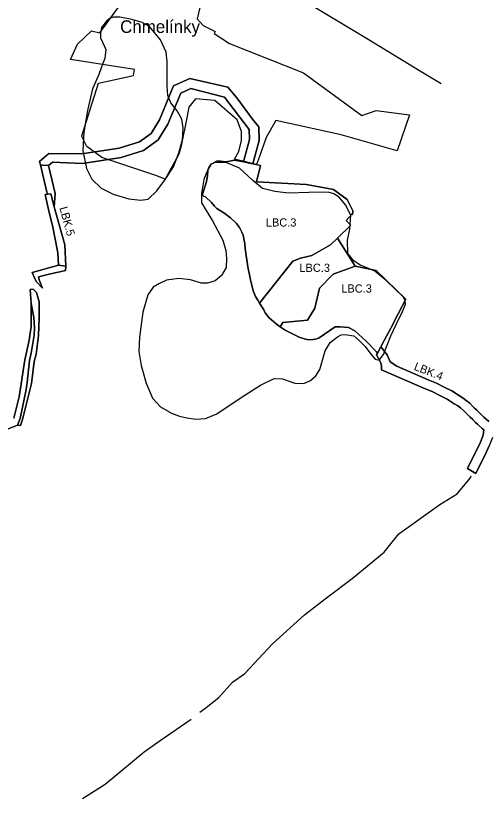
# Model space of a CAD drawing. Extents: x -555426 to -553015, y -1186745 to -1182595.
# Drawn here: x -554287 to -553542, y -1186745 to -1185506 of the extents above; entities that cross this region are included whole.
import ezdxf

# ---------------------------------------------------------------- set-up
doc = ezdxf.new("R2010")
doc.units = 0
for name, color, linetype in [('Level 10', 7, 'Continuous'), ('Level 12', 7, 'Continuous'), ('Level 14', 7, 'Continuous'), ('Level 51', 7, 'Continuous'), ('svahove_deformace', 7, 'Continuous'), ('USES_ID', 7, 'Continuous'), ('USES_LBC_navrh', 7, 'Continuous'), ('USES_LBC_stav', 7, 'Continuous'), ('USES_LBK_navrh', 7, 'Continuous'), ('USES_LBK_stav', 7, 'Continuous')]:
    doc.layers.add(name, color=color, linetype=linetype)

msp = doc.modelspace()

# ---------------------------------------------------------------- linework, layer by layer
at = {"layer": 'Level 10'}
msp.add_lwpolyline([(-553975.4, -1185407.1), (-553999.7, -1185510.6), (-553990.3, -1185521.1), (-553971.3, -1185530.6), (-553972.7, -1185533.8), (-553948.4, -1185549.8), (-553831.6, -1185596.5), (-553739, -1185663.9), (-553716.5, -1185656), (-553663.6, -1185662.6), (-553683.4, -1185719.5), (-553771.6, -1185694.6), (-553875.2, -1185671.9), (-553890.2, -1185698.9), (-553900.8, -1185728.5), (-553905.9, -1185741.4), (-553940.6, -1185733.1), (-553933.4, -1185720.8), (-553929.5, -1185703.6), (-553929.5, -1185689.1), (-553936.1, -1185670.6), (-553971.8, -1185640.1), (-554002.2, -1185637.5), (-554012.8, -1185650.7), (-554016.1, -1185667.5), (-554024.7, -1185711.6), (-554028.7, -1185724.8), (-554049.9, -1185764.5), (-554065, -1185758.6), (-554150.4, -1185730.1), (-554174.2, -1185712.9), (-554181.7, -1185697.3), (-554181.9, -1185696), (-554155.7, -1185612.4), (-554100.1, -1185600.4), (-554098.8, -1185591.2), (-554200.1, -1185574.9), (-554188.6, -1185550.7), (-554166.6, -1185529.6), (-554153.6, -1185532.9), (-554122.2, -1185490.3)], dxfattribs=at)
at = {"layer": 'Level 12'}
for points in [[(-553911.7, -1185740.4), (-553901.7, -1185703.4), (-553902.2, -1185681.8), (-553910.4, -1185671.8), (-553936.7, -1185635.6), (-553950.9, -1185618.8), (-554011.3, -1185605.1), (-554036.9, -1185617.1), (-554059.2, -1185670.5), (-554072.4, -1185692.2), (-554091, -1185705.4), (-554123, -1185715.5), (-554181.9, -1185724.6), (-554234, -1185724.1), (-554248.9, -1185736.6), (-554247.6, -1185742.1), (-554237.4, -1185785.1), (-554235.8, -1185788.4), (-554240, -1185789.1), (-554233.4, -1185817.2), (-554228.1, -1185837.8), (-554220, -1185881.2), (-554219, -1185900.7)], [(-554219, -1185900.7), (-554260.6, -1185912.2), (-554256.7, -1185920.6), (-554254.1, -1185926.6), (-554244.3, -1185937.4), (-554249.6, -1185923.8), (-554250.3, -1185919.1), (-554231.4, -1185914.6), (-554219.4, -1185911.8), (-554216.8, -1185911.1), (-554208, -1185909), (-554207.5, -1185902.6), (-554208.9, -1185868.4), (-554225.5, -1185808.2), (-554224.1, -1185787.4), (-554234.7, -1185743.1), (-554228.1, -1185737.6), (-554180.8, -1185739.6), (-554119.6, -1185730.2), (-554084.2, -1185719), (-554061.2, -1185702.6), (-554045.8, -1185677.3), (-554025.3, -1185628.3), (-554009.8, -1185620.9), (-553956.2, -1185634.8), (-553917.3, -1185685.8), (-553916.8, -1185701.6), (-553926.4, -1185737.4)], [(-554249.4, -1185959), (-554253.8, -1185944), (-554258.9, -1185938.8), (-554263.5, -1185939.1), (-554261.9, -1185961.7), (-554261.9, -1185997.8), (-554265.3, -1186019.4), (-554272.3, -1186050.7), (-554281.2, -1186109.2), (-554289.5, -1186143)], [(-554377.3, -1186191), (-554283.7, -1186154), (-554278.9, -1186154.8), (-554275.9, -1186144.9), (-554261.8, -1186087.9), (-554257.2, -1186053.5), (-554254.2, -1186041.6), (-554250.5, -1186012.3), (-554249.2, -1185984.3), (-554249.4, -1185959)], [(-553538.1, -1186148.4), (-553546, -1186141.3), (-553548.7, -1186138.9), (-553553, -1186134.5), (-553557.1, -1186130.6), (-553560.6, -1186127.2), (-553563.8, -1186123.8), (-553568.3, -1186119.3), (-553574.1, -1186115), (-553578.7, -1186111.4), (-553584.6, -1186107.6), (-553596.5, -1186099.9), (-553608.8, -1186093.7), (-553621.2, -1186087.4), (-553633.9, -1186082.1), (-553683.5, -1186060.8), (-553694.2, -1186053.6), (-553699.1, -1186042.7), (-553709.2, -1186029.9)], [(-553714.5, -1186040.1), (-553716, -1186043), (-553709.2, -1186055.2), (-553707.9, -1186060.7), (-553707.8, -1186066.7), (-553639.7, -1186095.9), (-553627.6, -1186101), (-553615.6, -1186107), (-553604, -1186112.9), (-553592.8, -1186120.2), (-553587.3, -1186123.7), (-553583.1, -1186126.9), (-553578.2, -1186130.7), (-553574.5, -1186134.4), (-553571.2, -1186137.7), (-553567.7, -1186141.3), (-553563.5, -1186145.2), (-553559.1, -1186149.7), (-553556.1, -1186152.4), (-553548, -1186159.7), (-553546.2, -1186161.3), (-553547, -1186170), (-553551.5, -1186181.2), (-553571.7, -1186222.8), (-553558.8, -1186230.6), (-553551.7, -1186216.3), (-553544.7, -1186202.1), (-553537.6, -1186186.9)]]:
    msp.add_lwpolyline(points, dxfattribs=at)
at = {"layer": 'Level 14'}
msp.add_lwpolyline([(-553940.3, -1185734.7), (-553953.7, -1185737.4), (-553967.2, -1185735.6), (-553977.6, -1185741.1), (-553982.8, -1185750.6), (-553983.4, -1185759.1), (-553984.9, -1185768.3), (-553991.5, -1185790.7), (-553986.1, -1185792.8), (-553977.1, -1185801.5), (-553972.2, -1185807.6), (-553968.2, -1185811), (-553955.7, -1185819.2), (-553950.7, -1185823), (-553946.8, -1185825.9), (-553937.5, -1185834.6), (-553932.6, -1185841.2), (-553928.7, -1185848.7), (-553926.8, -1185853.5), (-553925, -1185861.8), (-553924.3, -1185866.6), (-553923.7, -1185874.2), (-553919.6, -1185903.6), (-553916.2, -1185918.5), (-553914.7, -1185926.6), (-553912.2, -1185936.6), (-553911.1, -1185941.6), (-553907.2, -1185950.3), (-553903.5, -1185956.3), (-553900.7, -1185960.7), (-553893.9, -1185971.6), (-553892.2, -1185976.1), (-553885.6, -1185984.2), (-553874.4, -1185993.9), (-553868.1, -1185998.6), (-553860.1, -1186003.8), (-553838.1, -1186014.6), (-553828.2, -1186017.9), (-553822.7, -1186018.8), (-553816.2, -1186018.6), (-553810.1, -1186017.5), (-553806.4, -1186016.1), (-553781.2, -1185998.5), (-553773.2, -1185998.5), (-553759.9, -1185999.4), (-553750.1, -1186005), (-553733, -1186020.5), (-553715.8, -1186038), (-553714.5, -1186040.1), (-553709.2, -1186029.9), (-553704, -1186019.9), (-553693.4, -1186000.3), (-553681.6, -1185977.6), (-553669.6, -1185954.8), (-553716.6, -1185909.4), (-553749.5, -1185902.4), (-553777.3, -1185857.8), (-553756.3, -1185837.6), (-553763.7, -1185830.1), (-553754.7, -1185819.8), (-553753.8, -1185820.7), (-553753.1, -1185814.5), (-553762.3, -1185797), (-553784, -1185781.1), (-553826.5, -1185773.2), (-553905.7, -1185768.8), (-553899.3, -1185742.9), (-553940.3, -1185734.7)], dxfattribs=at)
at = {"layer": 'Level 51'}
for points in [[(-554064, -1185305.3), (-554054.3, -1185313), (-554015.3, -1185345.9), (-553963.7, -1185392), (-553941.6, -1185410.7), (-553882.9, -1185450.1), (-553831.9, -1185481.1), (-553729.3, -1185543.1), (-553648, -1185592.3), (-553613.8, -1185613.3)], [(-553995.2, -1186608.6), (-553985.5, -1186601.4), (-553965.2, -1186585.4), (-553943.8, -1186560.8), (-553924.1, -1186547.3), (-553881.1, -1186500.9), (-553829.5, -1186454.6), (-553797.2, -1186429.2), (-553754.2, -1186397.1), (-553703.6, -1186355.1), (-553680.7, -1186326.3), (-553615.9, -1186279.5), (-553588.3, -1186262.7), (-553567.9, -1186238.2), (-553566, -1186234.2)], [(-554180.7, -1186745), (-554145.3, -1186722.8), (-554083.6, -1186671.3), (-554057.8, -1186653.2), (-554009.1, -1186619.5)]]:
    msp.add_lwpolyline(points, dxfattribs=at)
at = {"layer": 'svahove_deformace'}
for points in [[(-554063.2, -1185783.2), (-554051.2, -1185766.8), (-554036.9, -1185745.3), (-554028.3, -1185722.7), (-554022.9, -1185702.3), (-554021.9, -1185683.5), (-554023.6, -1185669.8), (-554031.4, -1185656.5), (-554041.3, -1185643.9), (-554045.7, -1185631.9), (-554046.8, -1185617.2), (-554047.1, -1185578.3), (-554048.5, -1185563.3), (-554057.7, -1185544.2), (-554074.8, -1185523), (-554086.4, -1185516.5), (-554102.8, -1185511.7), (-554121.9, -1185508.3), (-554132.1, -1185508.3), (-554137.3, -1185509.7), (-554143.1, -1185514.5), (-554150.6, -1185524.7), (-554152.6, -1185533.6), (-554152.6, -1185541.1), (-554146.1, -1185554.8), (-554144.1, -1185559.5), (-554144.8, -1185568.4), (-554145.4, -1185573.5), (-554149.2, -1185582.4), (-554155, -1185598.8), (-554165.2, -1185621.7), (-554173.1, -1185655.8), (-554178.9, -1185690), (-554180.6, -1185719), (-554174.8, -1185747.7), (-554166.3, -1185764.4), (-554151.2, -1185778.7), (-554132.5, -1185788.6), (-554107.5, -1185795.5), (-554088.4, -1185797.8), (-554076.8, -1185796.1), (-554063.2, -1185783.2)], [(-553896.2, -1185779.4), (-553911.6, -1185766.8), (-553932.4, -1185747), (-553946.4, -1185741.2), (-553953.9, -1185738.4), (-553966.9, -1185738.1), (-553972.7, -1185738.8), (-553978.1, -1185740.8), (-553980.9, -1185745.6), (-553989.1, -1185765.1), (-553992.8, -1185787.3), (-553992.5, -1185801.9), (-553975.1, -1185830.6), (-553958.7, -1185861), (-553954.2, -1185877.4), (-553952.9, -1185890), (-553953.9, -1185904.7), (-553961.1, -1185917), (-553971.3, -1185925.5), (-553983.3, -1185929.3), (-553992.8, -1185929.3), (-554009.9, -1185924.2), (-554028.7, -1185921.8), (-554047.8, -1185924.5), (-554060.4, -1185930.3), (-554069.3, -1185935.4), (-554077.5, -1185947.7), (-554085.4, -1185975.4), (-554090.8, -1186014.7), (-554091.8, -1186037.5), (-554088.1, -1186059.4), (-554080.2, -1186087.4), (-554070, -1186111.6), (-554057.7, -1186125.3), (-554039.9, -1186135.2), (-554027.3, -1186140), (-554016, -1186142.7), (-554001.7, -1186144.7), (-553986.3, -1186143.7), (-553968.2, -1186136.2), (-553929.7, -1186110.3), (-553899.6, -1186090.8), (-553877.8, -1186080.5), (-553864.5, -1186080.9), (-553845, -1186087.7), (-553831, -1186088.1), (-553820.1, -1186083.6), (-553811.9, -1186075.8), (-553805.4, -1186066.2), (-553797.2, -1186036.2), (-553789.3, -1186023.2), (-553777.7, -1186014.3), (-553771.9, -1186010.9), (-553765.8, -1186010.6), (-553751.8, -1186012.9), (-553742.9, -1186020.5), (-553733.7, -1186029.7), (-553724.8, -1186041.6), (-553718, -1186049.5), (-553711.8, -1186051.2), (-553705, -1186042.3), (-553693.1, -1186012.9), (-553680.1, -1185984.6), (-553675.6, -1185976.8), (-553669.8, -1185962.4), (-553670.5, -1185957.3), (-553673.9, -1185950.8), (-553700.9, -1185924.5), (-553718.7, -1185910.5), (-553732.3, -1185904.4), (-553741.9, -1185901), (-553751.8, -1185894.1), (-553761.3, -1185882.5), (-553762, -1185861), (-553757.9, -1185843.6), (-553756.6, -1185821.4), (-553764.8, -1185805.4), (-553774.7, -1185793.1), (-553783.5, -1185787.6), (-553792.1, -1185785.2), (-553822.8, -1185785.6), (-553854.9, -1185786.9), (-553876.7, -1185783.9), (-553896.2, -1185779.4)]]:
    msp.add_lwpolyline(points, dxfattribs=at)
at = {"layer": 'USES_LBC_navrh'}
for p, q in [((-553788.7, -1185868.8), (-553777.3, -1185857.8)), ((-553777.3, -1185857.8), (-553749.5, -1185902.4)), ((-553818.4, -1185885.3), (-553788.7, -1185868.8)), ((-553900.7, -1185960.7), (-553848.1, -1185894.5)), ((-553749.5, -1185902.4), (-553784.2, -1185915)), ((-553784.2, -1185915), (-553806.1, -1185937)), ((-553893.9, -1185971.6), (-553900.7, -1185960.7)), ((-553892.2, -1185976.1), (-553893.9, -1185971.6)), ((-553885.6, -1185984.2), (-553892.2, -1185976.1)), ((-553874.4, -1185993.9), (-553885.6, -1185984.2)), ((-553868.1, -1185998.6), (-553874.4, -1185993.9)), ((-553864, -1185991.5), (-553868.1, -1185998.6)), ((-553825.1, -1185988.1), (-553864, -1185991.5))]:
    msp.add_line(p, q, dxfattribs=at)
for points in [[(-553848.1, -1185894.5), (-553836.1, -1185889.5), (-553818.4, -1185885.3)], [(-553806.1, -1185937), (-553813.2, -1185969.1), (-553825.1, -1185988.1)]]:
    msp.add_lwpolyline(points, dxfattribs=at)
at = {"layer": 'USES_LBC_stav'}
for p, q in [((-553868.1, -1185998.6), (-553864, -1185991.5)), ((-553864, -1185991.5), (-553825.1, -1185988.1))]:
    msp.add_line(p, q, dxfattribs=at)
for points in [[(-553900.7, -1185960.7), (-553903.5, -1185956.3), (-553907.2, -1185950.3), (-553911.1, -1185941.6), (-553912.2, -1185936.6), (-553914.7, -1185926.6), (-553916.2, -1185918.5), (-553919.6, -1185903.6), (-553923.7, -1185874.2), (-553924.3, -1185866.6), (-553925, -1185861.8), (-553926.8, -1185853.5), (-553928.7, -1185848.7), (-553932.6, -1185841.2), (-553937.5, -1185834.6), (-553946.8, -1185825.9), (-553950.7, -1185823), (-553955.7, -1185819.2), (-553968.2, -1185811), (-553972.2, -1185807.6), (-553977.1, -1185801.5), (-553986.1, -1185792.8), (-553991.5, -1185790.7), (-553984.9, -1185768.3), (-553983.4, -1185759.1), (-553982.8, -1185750.6), (-553977.6, -1185741.1), (-553967.2, -1185735.6), (-553953.7, -1185737.4), (-553940.3, -1185734.7)], [(-553940.3, -1185734.7), (-553926.4, -1185737.4), (-553911.7, -1185740.4), (-553899.3, -1185742.9), (-553905.7, -1185768.8), (-553826.5, -1185773.2), (-553784, -1185781.1), (-553762.3, -1185797), (-553753.1, -1185814.5), (-553753.8, -1185820.7), (-553754.7, -1185819.8), (-553763.7, -1185830.1), (-553756.3, -1185837.6), (-553777.3, -1185857.8)], [(-553777.3, -1185857.8), (-553788.7, -1185868.8), (-553818.4, -1185885.3), (-553836.1, -1185889.5), (-553848.1, -1185894.5), (-553900.7, -1185960.7)], [(-553749.5, -1185902.4), (-553716.6, -1185909.4), (-553669.6, -1185954.8), (-553681.6, -1185977.6), (-553693.4, -1186000.3), (-553704, -1186019.9), (-553709.2, -1186029.9), (-553714.5, -1186040.1), (-553715.8, -1186038), (-553733, -1186020.5), (-553750.1, -1186005), (-553759.9, -1185999.4), (-553773.2, -1185998.5), (-553781.2, -1185998.5), (-553806.4, -1186016.1), (-553810.1, -1186017.5), (-553816.2, -1186018.6), (-553822.7, -1186018.8), (-553828.2, -1186017.9), (-553838.1, -1186014.6), (-553860.1, -1186003.8), (-553868.1, -1185998.6)], [(-553825.1, -1185988.1), (-553813.2, -1185969.1), (-553806.1, -1185937), (-553784.2, -1185915), (-553749.5, -1185902.4)]]:
    msp.add_lwpolyline(points, dxfattribs=at)
at = {"layer": 'USES_LBK_navrh'}
for p, q in [((-554247.6, -1185742.1), (-554244.1, -1185742.4)), ((-554244.1, -1185742.4), (-554234.7, -1185743.1)), ((-554231.2, -1185787.7), (-554235.8, -1185788.4)), ((-554225.5, -1185808.2), (-554231.2, -1185787.7)), ((-554219, -1185900.7), (-554207.5, -1185902.6)), ((-554219.4, -1185911.8), (-554231.4, -1185914.6)), ((-554231.4, -1185914.6), (-554250.3, -1185919.1)), ((-554261.9, -1185961.7), (-554257.8, -1185983.7)), ((-554257.8, -1185983.7), (-554256.9, -1185999.8)), ((-554256.9, -1185999.8), (-554257.4, -1186011.8)), ((-554257.4, -1186011.8), (-554262, -1186040.2)), ((-553714.5, -1186040.1), (-553709.2, -1186029.9)), ((-553709.2, -1186029.9), (-553699.1, -1186042.7)), ((-554262, -1186040.2), (-554265, -1186051.9)), ((-554265, -1186051.9), (-554268.4, -1186086.8)), ((-554270, -1186097.7), (-554279.7, -1186143.6)), ((-554268.4, -1186086.8), (-554270, -1186097.7)), ((-553615.6, -1186107), (-553627.6, -1186101)), ((-553604, -1186112.9), (-553615.6, -1186107)), ((-553578.7, -1186111.4), (-553574.1, -1186115)), ((-553592.8, -1186120.2), (-553604, -1186112.9)), ((-553587.3, -1186123.7), (-553592.8, -1186120.2)), ((-553574.1, -1186115), (-553568.3, -1186119.3)), ((-553574.5, -1186134.4), (-553578.2, -1186130.7)), ((-554279.7, -1186143.6), (-554283.7, -1186154)), ((-554283.7, -1186154), (-554377.3, -1186191)), ((-553548, -1186159.7), (-553556.1, -1186152.4))]:
    msp.add_line(p, q, dxfattribs=at)
for points in [[(-554235.8, -1185788.4), (-554237.4, -1185785.1), (-554247.6, -1185742.1)], [(-554234.7, -1185743.1), (-554224.1, -1185787.4), (-554225.5, -1185808.2)], [(-554256.7, -1185920.6), (-554260.6, -1185912.2), (-554219, -1185900.7)], [(-554207.5, -1185902.6), (-554208, -1185909), (-554216.8, -1185911.1), (-554219.4, -1185911.8)], [(-554244.3, -1185937.4), (-554254.1, -1185926.6), (-554256.7, -1185920.6)], [(-554250.3, -1185919.1), (-554249.6, -1185923.8), (-554244.3, -1185937.4)], [(-554265.3, -1186019.4), (-554261.9, -1185997.8), (-554261.9, -1185961.7)], [(-554289.5, -1186143), (-554281.2, -1186109.2), (-554272.3, -1186050.7), (-554265.3, -1186019.4)], [(-553707.8, -1186066.7), (-553707.9, -1186060.7), (-553709.2, -1186055.2), (-553716, -1186043), (-553714.5, -1186040.1)], [(-553699.1, -1186042.7), (-553694.2, -1186053.6), (-553683.5, -1186060.8), (-553633.9, -1186082.1), (-553621.2, -1186087.4), (-553608.8, -1186093.7)], [(-553627.6, -1186101), (-553639.7, -1186095.9), (-553707.8, -1186066.7)], [(-553608.8, -1186093.7), (-553596.5, -1186099.9), (-553584.6, -1186107.6), (-553578.7, -1186111.4)], [(-553578.2, -1186130.7), (-553583.1, -1186126.9), (-553587.3, -1186123.7)], [(-553568.3, -1186119.3), (-553563.8, -1186123.8), (-553560.6, -1186127.2), (-553557.1, -1186130.6)], [(-553567.7, -1186141.3), (-553571.2, -1186137.7), (-553574.5, -1186134.4)], [(-553557.1, -1186130.6), (-553553, -1186134.5), (-553548.7, -1186138.9), (-553546, -1186141.3), (-553538.1, -1186148.4)], [(-553556.1, -1186152.4), (-553559.1, -1186149.7), (-553563.5, -1186145.2), (-553567.7, -1186141.3)], [(-553547, -1186170), (-553546.2, -1186161.3), (-553548, -1186159.7)], [(-553558.8, -1186230.6), (-553571.7, -1186222.8), (-553551.5, -1186181.2), (-553547, -1186170)], [(-553532.3, -1186173.6), (-553537.6, -1186186.9), (-553544.7, -1186202.1), (-553551.7, -1186216.3), (-553558.8, -1186230.6)]]:
    msp.add_lwpolyline(points, dxfattribs=at)
at = {"layer": 'USES_LBK_stav'}
for p, q in [((-553911.7, -1185740.4), (-553926.4, -1185737.4)), ((-554244.1, -1185742.4), (-554247.6, -1185742.1)), ((-554234.7, -1185743.1), (-554244.1, -1185742.4)), ((-554235.8, -1185788.4), (-554231.2, -1185787.7)), ((-554231.2, -1185787.7), (-554225.5, -1185808.2)), ((-554207.5, -1185902.6), (-554219, -1185900.7)), ((-554257.8, -1185983.7), (-554261.9, -1185961.7)), ((-554256.9, -1185999.8), (-554257.8, -1185983.7)), ((-554257.4, -1186011.8), (-554256.9, -1185999.8)), ((-554262, -1186040.2), (-554257.4, -1186011.8)), ((-554265, -1186051.9), (-554262, -1186040.2)), ((-554268.4, -1186086.8), (-554265, -1186051.9)), ((-554279.7, -1186143.6), (-554270, -1186097.7)), ((-554270, -1186097.7), (-554268.4, -1186086.8)), ((-554283.7, -1186154), (-554279.7, -1186143.6))]:
    msp.add_line(p, q, dxfattribs=at)
for points in [[(-554247.6, -1185742.1), (-554248.9, -1185736.6), (-554234, -1185724.1), (-554181.9, -1185724.6), (-554123, -1185715.5), (-554091, -1185705.4), (-554072.4, -1185692.2), (-554059.2, -1185670.5), (-554036.9, -1185617.1), (-554011.3, -1185605.1), (-553950.9, -1185618.8), (-553936.7, -1185635.6), (-553910.4, -1185671.8), (-553902.2, -1185681.8), (-553901.7, -1185703.4), (-553911.7, -1185740.4)], [(-553926.4, -1185737.4), (-553916.8, -1185701.6), (-553917.3, -1185685.8), (-553956.2, -1185634.8), (-554009.8, -1185620.9), (-554025.3, -1185628.3), (-554045.8, -1185677.3), (-554061.2, -1185702.6), (-554084.2, -1185719), (-554119.6, -1185730.2), (-554180.8, -1185739.6), (-554228.1, -1185737.6), (-554234.7, -1185743.1)], [(-554219, -1185900.7), (-554220, -1185881.2), (-554228.1, -1185837.8), (-554233.4, -1185817.2), (-554240, -1185789.1), (-554235.8, -1185788.4)], [(-554225.5, -1185808.2), (-554208.9, -1185868.4), (-554207.5, -1185902.6)], [(-554261.9, -1185961.7), (-554263.5, -1185939.1), (-554258.9, -1185938.8), (-554253.8, -1185944), (-554249.4, -1185959)], [(-554249.4, -1185959), (-554249.2, -1185984.3), (-554250.5, -1186012.3), (-554254.2, -1186041.6), (-554257.2, -1186053.5), (-554261.8, -1186087.9), (-554275.9, -1186144.9), (-554278.9, -1186154.8), (-554283.7, -1186154)]]:
    msp.add_lwpolyline(points, dxfattribs=at)

# ---------------------------------------------------------------- texts
at = {"layer": 'Level 10'}
msp.add_text('Chmelínky', height=20, dxfattribs=at).set_placement((-554121.4, -1185533.1))
at = {"layer": 'USES_ID'}
for s, rotation, p in [('LBK.5', 285.2387, (-554217.5, -1185810)), ('LBK.4', 338.743, (-553657.7, -1186066.2))]:
    msp.add_text(s, height=13, rotation=rotation, dxfattribs=at).set_placement(p)
for p in [(-553890.9, -1185839.6), (-553837.8, -1185911.4), (-553771.5, -1185944.2)]:
    msp.add_text('LBC.3', height=13, dxfattribs=at).set_placement(p)

doc.saveas('drawing.dxf')
